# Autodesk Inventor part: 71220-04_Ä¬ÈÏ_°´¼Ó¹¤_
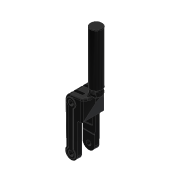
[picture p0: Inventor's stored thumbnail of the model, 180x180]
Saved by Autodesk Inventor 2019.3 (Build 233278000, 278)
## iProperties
Created: 2010-06
Part Number: 71220-04_Ä¬ÈÏ_°´¼Ó¹¤_
Material: Ogólny
Document SubType Name: Modeling
Designer: CADENGINEERING4
Density: 1 g/cm^3
Appearance: Gładki — czarny
Author: CADENGINEERING4
Revision Number: ÈÎºÎ
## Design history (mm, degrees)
feature "NONE"
feature "NONE:1"
node "Bryła1"
node "Bryła2"
